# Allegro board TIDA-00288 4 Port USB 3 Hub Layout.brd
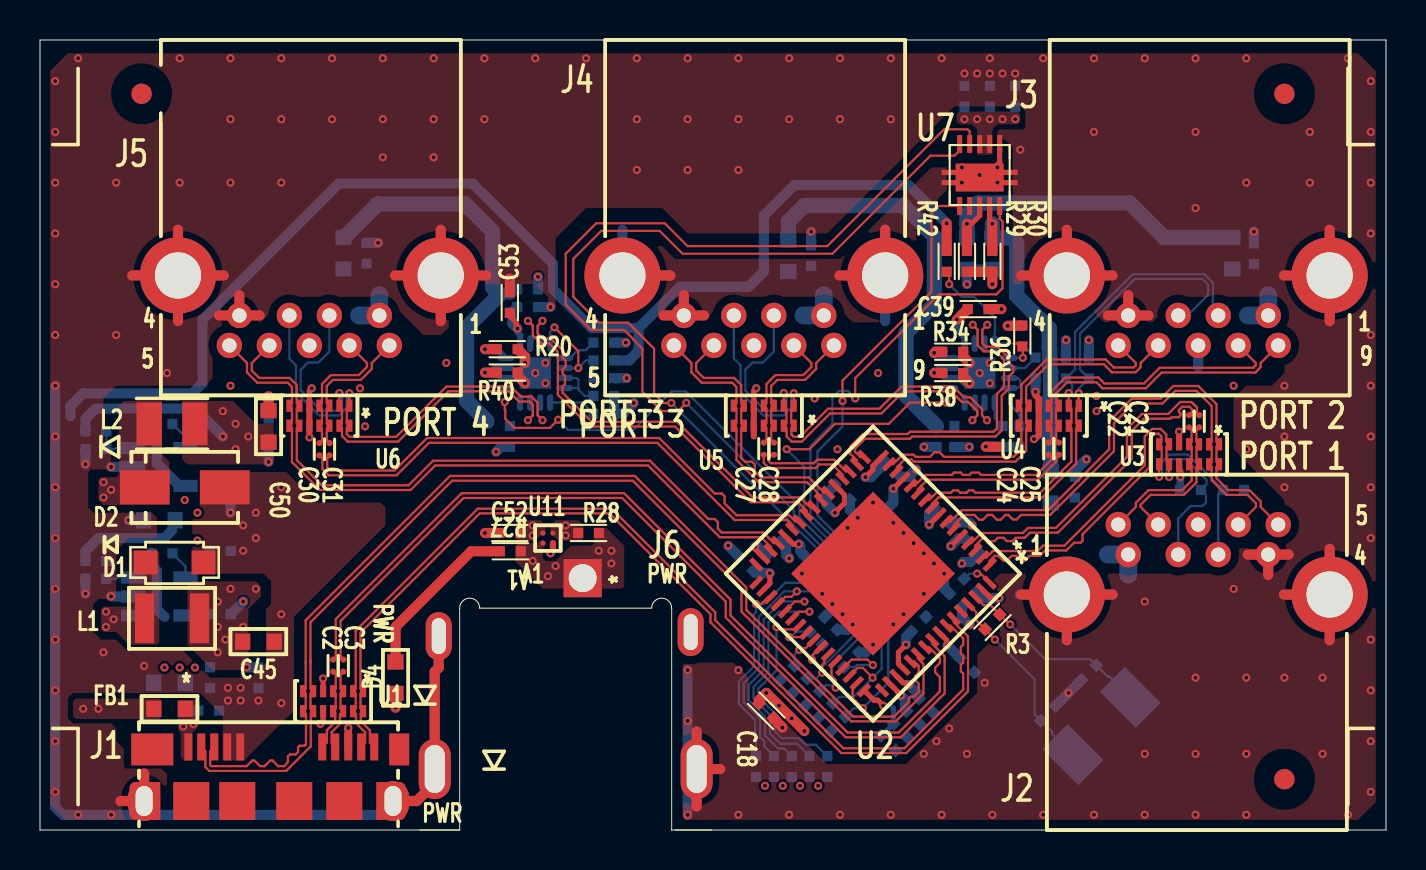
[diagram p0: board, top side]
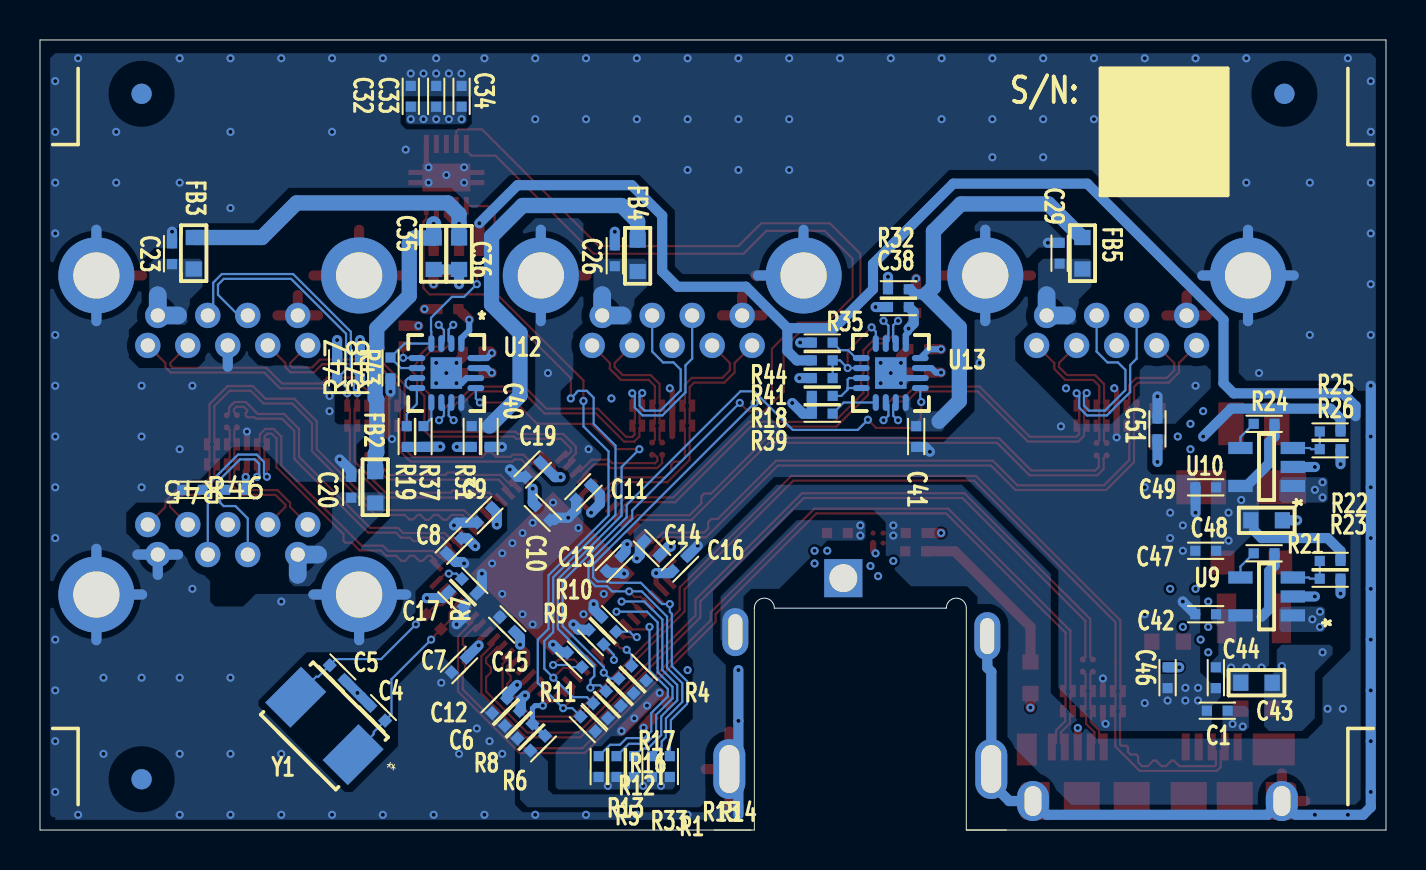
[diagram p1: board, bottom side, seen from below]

Outline 67.31 x 39.52 mm; copper layers: TOP, L2_GND, L3_PWR, BOTTOM. Coordinates in mm from the lower left corner of the outline.
Outline path: 0,0 0,39.52 67.31,39.52 67.31,0 31.75,0

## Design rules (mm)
net group DP_DN1: nets DM_DN1 DP_DN1
net group DP_DN2: nets DM_DN2 DP_DN2
net group DP_DN3: nets DM_DN3 DP_DN3
net group DP_DN4: nets DM_DN4 DP_DN4
net group DP_HUB_SSTX_P3: nets HUB_SSTXM_P3 HUB_SSTXP_P3
net group DP_HUB_SSTX_P4: nets HUB_SSTXM_P4 HUB_SSTXP_P4
net group DP_OUT3: nets DM_OUT3 DP_OUT3
net group DP_OUT4: nets DM_OUT4 DP_OUT4
net group DP_SSRX_DN1: nets SSRXM_DN1 SSRXP_DN1
net group DP_SSRX_DN2: nets SSRXM_DN2 SSRXP_DN2
net group DP_SSRX_DN3: nets SSRXM_DN3 SSRXP_DN3
net group DP_SSRX_DN4: nets SSRXM_DN4 SSRXP_DN4
net group DP_SSRX_UP: nets SSRXM_UP SSRXP_UP
net group DP_SSTX_DN1: nets SSTXM_DN1 SSTXP_DN1
net group DP_SSTX_DN2: nets SSTXM_DN2 SSTXP_DN2
net group DP_SSTX_DN3: nets SSTXM_DN3 SSTXP_DN3
net group DP_SSTX_DN4: nets SSTXM_DN4 SSTXP_DN4
net group DP_SSTX_P1: nets HUB_SSTXM_P1 HUB_SSTXP_P1
net group DP_SSTX_P2: nets HUB_SSTXM_P2 HUB_SSTXP_P2
net group DP_SSTX_PUP: nets SSTXM_PUP SSTXP_PUP
net group DP_SSTX_UP: nets SSTXM_UP SSTXP_UP
net group DP_UP: nets DM_UP DP_UP
nets with their own width: min track width 0.109; nets GRST#
nets with their own width: min track width 0.508; nets VBUS_IN VBUS_OUT_PORT_1 VBUS_OUT_PORT_2 VBUS_OUT_PORT_3 VBUS_OUT_PORT_4 VBUS_P1_FB VBUS_P2_FB VBUS_P3_FB VBUS_P4_FB VBUS_PUP_FB

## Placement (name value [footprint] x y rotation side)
C1  0.1uF  [0402]  8.44 5.97 0 bottom
C2  0.1uF  [0201RND]  14.66 8.23 90 top
C3  0.1uF  [0201RND]  15.17 8.23 90 top
C4  18pF  [0402]  50.42 5.84 45 bottom
C5  18pF  [0402]  52.45 7.87 225 bottom
C6  1uF  [0402]  43.69 5.59 315 bottom
C7  .01uF  [0402]  46.35 8.26 315 bottom
C8  .01uF  [0402]  46.61 14.22 315 bottom
C9  0.1uF  [0402]  45.09 15.75 315 bottom
C10  0.1uF  [0402]  42.16 15.88 225 bottom
C11  0.1uF  [0402]  40.13 16.89 315 bottom
C12  .01uF  [0402]  44.32 6.22 315 bottom
C13  .01uF  [0402]  38.61 13.34 315 bottom
C14  10uF  [0402]  36.7 14.1 45 bottom
C15  .01uF  [0402]  43.94 10.29 45 bottom
C16  .01uF  [0402]  35.31 13.34 135 bottom
C17  0.1uF  [0402]  46.48 11.56 225 bottom
C18  0.1uF  [0402]  36.32 5.97 315 top
C19  10uF  [0402]  42.67 18.03 315 bottom
C20  0.1uF  [0402]  51.75 17.15 90 bottom
C21  0.1uF  [0201RND]  57.97 20.45 90 top
C22  0.1uF  [0201RND]  57.46 20.45 90 top
C23  0.1uF  [0402]  60.71 28.83 90 bottom
C24  0.1uF  [0201RND]  50.45 19.08 270 top
C25  0.1uF  [0201RND]  50.95 19.08 270 top
C26  0.1uF  [0402]  38.57 28.73 90 bottom
C27  0.1uF  [0201RND]  36.2 19.08 270 top
C28  0.1uF  [0201RND]  36.7 19.08 270 top
C29  0.1uF  [0402]  16.32 28.85 90 bottom
C30  0.1uF  [0201RND]  13.97 19.05 270 top
C31  0.1uF  [0201RND]  14.48 19.05 270 top
C32  0.1uF  [0402]  48.77 36.7 90 bottom
C33  4.7uF  [0402]  47.5 36.7 90 bottom
C34  0.1uF  [0402]  46.23 36.7 90 bottom
C35  22uF  [0603]  47.62 28.83 270 bottom
C36  22uF  [0603]  46.35 28.83 270 bottom
C38  4.7uF  [0402]  24.38 26.16 0 bottom
C39  0.1uF  [0402]  46.91 26.06 0 top
C40  10uF  [0402]  44.83 19.69 270 bottom
C41  10uF  [0402]  23.5 19.69 270 bottom
C42  2.2uF  [0402]  9.02 10.8 0 bottom
C43  22uF  [0603]  6.48 7.37 180 bottom
C44  0.1uF  [0402]  8.51 7.62 270 bottom
C45  22uF  [0603]  10.92 9.42 0 top
C46  2.2uF  [0402]  10.92 7.62 270 bottom
C47  2.2uF  [0402]  9.02 13.97 0 bottom
C48  22uF  [0603]  5.97 15.49 180 bottom
C49  0.1uF  [0402]  9.02 17.15 0 bottom
C50  22uF  [0603]  11.43 20.19 90 top
C51  2.2uF  [0402]  11.43 20.07 90 bottom
C52  10uF  [0402]  23.5 14.86 180 top
C53  0.1uF  [0402]  23.5 26.39 90 top
D1  MBR0520LT1G  [SOD123F]  6.73 13.39 180 top
D2  B130-13-F  [SMA]  7.24 17.15 180 top
D4  LED  [0603]  17.78 7.62 90 top
FB1  220 @ 100MHZ, 2A  [0603]  6.48 6.07 180 top
FB2  220 @ 100MHZ,2A  [0603]  50.55 17.15 90 bottom
FB3  220 @ 100MHZ,2A  [0603]  59.62 28.85 90 bottom
FB4  220 @ 100MHZ,2A  [0603]  37.42 28.73 90 bottom
FB5  220 @ 100MHZ,2A  [0603]  15.18 28.85 90 bottom
J1  USB3_MICRO_B  [CON_SMRT_10_USB3_ZX360D-B]  11.43 1.45 0 top
J2  USB3_TYPEA_CONNECTOR  [USB3_TYPEA]  57.92 15.28 0 top
J3  USB3_TYPEA_CONNECTOR  [USB3_TYPEA]  57.92 24.24 180 top
J4  USB3_TYPEA_CONNECTOR  [USB3_TYPEA]  35.7 24.24 180 top
J5  USB3_TYPEA_CONNECTOR  [USB3_TYPEA]  13.47 24.24 180 top
J6  DC_PWR_JACK  [JACK_PJ-068]  27.14 12.59 90 top
L1  6.8uH@700mA  [1210]  6.6 10.59 0 top
L2  2.2uH@1.3A  [IND_1008]  6.6 20.32 0 top
NOREF  -  []  67.31 39.37 0 top
NOREF#2  -  []  20.95 29.08 0 top
NOREF#3  -  []  49.54 39.37 0 top
NOREF#4  -  []  0 0 0 top
NOREF#5  -  []  64.4 0 0 top
NOREF#6  -  []  67.31 39.37 0 top
NOREF#7  -  [unnamed#2]  62.23 36.83 0 top
NOREF#8  -  []  454.66 15.24 0 top
NOREF#9  -  []  0 0 0 top
NOREF#10  -  []  -25.4 -97.98 0 top
NOREF#11  -  []  0 0 0 top
NOREF#12  -  []  49.54 39.37 0 top
NOREF#13  -  []  67.31 39.37 0 top
NOREF#14  -  []  0 0 90 top
NOREF#15  -  []  67.31 39.37 0 top
NOREF#16  -  [unnamed#2]  5.08 36.83 0 top
NOREF#17  -  []  2.79 0.6 0 top
NOREF#18  -  []  21.37 11.59 0 top
NOREF#19  -  []  64.4 0 0 top
NOREF#20  -  []  0 39.52 0 top
NOREF#21  -  []  2.79 0.6 0 top
NOREF#22  -  []  27.93 39.37 0 top
NOREF#23  -  []  0 0 0 top
NOREF#24  -  []  0 0 0 top
NOREF#25  -  [unnamed#2]  62.23 2.54 0 top
NOREF#26  -  []  27.93 39.37 0 top
NOREF#27  -  []  0 0 90 top
NOREF#28  -  []  20.99 0 0 top
NOREF#29  -  [unnamed#2]  62.23 36.83 180 bottom
NOREF#30  -  []  21.26 34.93 180 bottom
NOREF#31  -  [unnamed#2]  62.23 2.54 180 bottom
NOREF#32  -  [unnamed#2]  5.08 36.83 180 bottom
NOREF#33  -  []  36.55 32.63 180 bottom
R1  DNI  [0402]  37.59 3.18 90 bottom
R3  DNI,1M  [0402]  47.62 10.41 45 top
R4  DNI  [0402]  37.36 7.85 45 bottom
R5  DNI  [0402]  39.37 3.18 90 bottom
R6  90.9K  [0402]  42.42 4.34 135 bottom
R7  9.1K  [0402]  45.85 12.19 225 bottom
R8  10k  [0402]  43.05 4.95 315 bottom
R9  10k  [0402]  39.5 9.65 45 bottom
R10  10k  [0402]  38.86 10.29 45 bottom
R11  10k  [0402]  40.58 8.52 45 bottom
R12  10k  [0402]  39.28 5.97 45 bottom
R13  10k  [0402]  39.9 5.31 45 bottom
R14  4.7K  [0402]  35.81 3.18 270 bottom
R15  4.7K  [0402]  36.7 3.18 270 bottom
R16  10k  [0402]  38.63 6.58 45 bottom
R17  10k  [0402]  38 7.21 45 bottom
R18  10k  [0402]  28.19 21.72 180 bottom
R19  10k  [0402]  48.97 19.69 90 bottom
R20  33.6K  [0402]  23.37 24.05 0 top
R21  10k  [0402]  6.1 13.84 0 bottom
R22  45.3K  [0402]  2.79 13.46 0 bottom
R23  10k  [0402]  2.79 12.57 180 bottom
R24  10k  [0402]  6.1 20.32 0 bottom
R25  8.25K  [0402]  2.79 19.94 0 bottom
R26  10k  [0402]  2.79 19.05 180 bottom
R27  290  [0402]  23.52 13.94 180 top
R28  10k  [0402]  27.43 14.86 180 top
R29  DNI  [0402]  47.62 28.45 90 top
R30  DNI  [0402]  46.35 28.45 90 top
R31  DNI  [0402]  45.72 19.69 90 bottom
R32  DNI  [0402]  24.38 27.05 180 bottom
R33  DNI  [0402]  38.48 3.18 90 bottom
R34  33.6K  [0402]  45.64 23.93 0 top
R35  10k  [0402]  28.19 24.38 180 bottom
R36  10k  [0402]  49.12 24.71 270 top
R37  10k  [0402]  48.13 19.69 90 bottom
R38  DNI  [0402]  45.64 22.86 0 top
R39  10k  [0402]  28.19 20.83 180 bottom
R40  DNI  [0402]  23.37 22.89 0 top
R41  47K  [0402]  28.19 22.61 0 bottom
R42  10k  [0402]  45.34 28.45 270 top
R43  47K  [0402]  49.78 23.11 270 bottom
R44  10k  [0402]  28.19 23.5 180 bottom
R45  62K  [0402]  59.69 17.02 0 bottom
R46  62K  [0402]  57.53 17.02 180 bottom
R47  62K  [0402]  52.45 23.11 90 bottom
R48  62K  [0402]  51.31 23.11 90 bottom
U1  TPD6E05U06  [UQFN_14_142X57_20]  14.66 6.45 180 top
U2  TUSB8041  [QFN_64_354SQ_20]  41.66 12.83 225 top
U3  TPD6E05U06  [UQFN_14_142X57_20]  57.46 18.8 180 top
U4  TPD6E05U06  [UQFN_14_142X57_20]  50.45 20.73 180 top
U5  TPD6E05U06  [UQFN_14_142X57_20]  36.2 20.73 180 top
U6  TPD6E05U06  [UQFN_14_142X57_20]  13.97 20.73 180 top
U7  TPS2003C  [DRC_S_PDSO_N10]  46.99 32.77 270 top
U9  LMR10510X  [SOT_23_5]  5.97 11.68 90 bottom
U10  LMR10510X  [SOT_23_5]  5.97 18.16 90 bottom
U11  TPS22910  [BGA_4_36SQ_20]  25.4 14.61 270 top
U12  TPS2546  [QFN_16_124X124_20]  46.99 22.86 270 bottom
U13  TPS2546  [QFN_16_124X124_20]  24.77 22.86 270 bottom
Y1  24MHz  [XTAL_2_SM_197X126]  53.09 5.21 45 bottom

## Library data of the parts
C1-C36 C38-C53 = CAP NP
D1 D2 = DIODE SCHOTTKY
D4 = LED
FB1-FB5 = FERRITE BEAD
J1 = USB3_MICRO_B
J2-J5 = USB3_TYPEA_CONNECTER
J6 = 6140046600_DC_PWR_JACK_0
L1 L2 = INDUCTOR
R1 R3-R48 = R
U1 U3-U6 = TPD6E05U06
U2 = TUSB8041
U7 = TPS2003C
U9 U10 = LMR10510X
U11 = TPS22910
U12 U13 = TPS2546
Y1 = CRYSTAL

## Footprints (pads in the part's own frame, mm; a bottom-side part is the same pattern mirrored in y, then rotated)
0201RND
  round 0.305 smd: 1(-0.305,0) 2(0.305,0)
0402
  rect 0.508x0.508 smd: 1(-0.521,0) 2(0.521,0)
0603
  rect 0.762x0.813 smd: 1(-0.787,0) 2(0.787,0)
1210
  rect 0.965x2.489 smd: 1(-1.372,0) 2(1.372,0)
BGA_4_36SQ_20
  round 0.254 smd: A1(0.25,-0.25) A2(-0.25,-0.25) B1(0.25,0.25) B2(-0.25,0.25)
CON_SMRT_10_USB3_ZX360D-B
  rect 2.1x1.6 smd: (-5.815,2.58)
  rect 1.8x1.9 smd: (-3.865,0) (-1.565,0) (1.285,0) (3.785,0)
  rect 1x1.6 smd: (6.535,2.58)
  rect 0.4x1.35 smd: 1(-4.015,2.705) 2(-3.365,2.705) 3(-2.715,2.705) 4(-2.065,2.705) 5(-1.415,2.705) 6(2.685,2.705) 7(3.335,2.705) 8(3.985,2.705) 9(4.635,2.705) 10(5.285,2.705)
  oval 1.6x2 hole 0.85x1.5: 11(-6.223,0) 12(6.223,0)
DRC_S_PDSO_N10
  rect 0.9x0.25 smd: 1(-1.55,1) 2(-1.55,0.5) 3(-1.55,0) 4(-1.55,-0.5) 5(-1.55,-1) 6(1.55,-1) 7(1.55,-0.5) 8(1.55,0) 9(1.55,0.5) 10(1.55,1)
  custom 0.35x0.35 smd: 11(0.125,0)
IND_1008
  rect 1.27x2.146 smd: 1(-1.143,0) 2(1.143,0)
JACK_PJ-068
  rect 1.905x1.905 hole 1.397: 1(0.005,0)
  oval 2.4x1.3 hole 1.8x0.7: 2(-2.895,7.2) 3(-2.695,-5.4)
  oval 3x1.6 hole 2.4x1: 4(-9.545,-5.7) 5(-9.545,7.4)
QFN_16_124X124_20
  oval 0.838x0.305 smd: 1(-1.475,0.75) 2(-1.475,0.25) 3(-1.475,-0.25) 4(-1.475,-0.75) 9(1.475,-0.75) 10(1.475,-0.25) 11(1.475,0.25) 12(1.475,0.75)
  oval 0.305x0.838 smd: 5(-0.75,-1.475) 6(-0.25,-1.475) 7(0.25,-1.475) 8(0.75,-1.475) 13(0.75,1.475) 14(0.25,1.475) 15(-0.25,1.475) 16(-0.75,1.475)
  rect 1.575x1.575 smd: 17(0,0)
QFN_64_354SQ_20
  rect 0.787x0.254 smd: 1(-4.445,3.81) 2(-4.445,3.302) 3(-4.445,2.794) 4(-4.445,2.286) 5(-4.445,1.778) 6(-4.445,1.27) 7(-4.445,0.762) 8(-4.445,0.254) 9(-4.445,-0.254) 10(-4.445,-0.762) 11(-4.445,-1.27) 12(-4.445,-1.778) 13(-4.445,-2.286) 14(-4.445,-2.794) 15(-4.445,-3.302) 16(-4.445,-3.81) 33(4.445,-3.81) 34(4.445,-3.302) 35(4.445,-2.794) 36(4.445,-2.286) 37(4.445,-1.778) 38(4.445,-1.27) 39(4.445,-0.762) 40(4.445,-0.254) 41(4.445,0.254) 42(4.445,0.762) 43(4.445,1.27) 44(4.445,1.778) 45(4.445,2.286) 46(4.445,2.794) 47(4.445,3.302) 48(4.445,3.81)
  rect 0.254x0.787 smd: 17(-3.81,-4.445) 18(-3.302,-4.445) 19(-2.794,-4.445) 20(-2.286,-4.445) 21(-1.778,-4.445) 22(-1.27,-4.445) 23(-0.762,-4.445) 24(-0.254,-4.445) 25(0.254,-4.445) 26(0.762,-4.445) 27(1.27,-4.445) 28(1.778,-4.445) 29(2.286,-4.445) 30(2.794,-4.445) 31(3.302,-4.445) 32(3.81,-4.445) 49(3.81,4.445) 50(3.302,4.445) 51(2.794,4.445) 52(2.286,4.445) 53(1.778,4.445) 54(1.27,4.445) 55(0.762,4.445) 56(0.254,4.445) 57(-0.254,4.445) 58(-0.762,4.445) 59(-1.27,4.445) 60(-1.778,4.445) 61(-2.286,4.445) 62(-2.794,4.445) 63(-3.302,4.445) 64(-3.81,4.445)
  rect 5.791x5.791 smd: 65(0,0)
SMA
  rect 2.489x1.702 smd: 1(-2,0) 2(2,0)
SOD123F
  rect 1.194x1.194 smd: 1(-1.448,0) 2(1.448,0)
SOT_23_5
  rect 0.61x1.219 smd: 1(-0.95,-1.31) 2(0,-1.31) 3(0.95,-1.31) 4(0.95,1.31) 5(-0.95,1.31)
unnamed#2
  round 1.016 smd: (0,0)
UQFN_14_142X57_20
  rect 0.305x0.61 smd: 1(-1.5,-0.5) 2(-1,-0.5) 3(-0.5,-0.5) 4(0,-0.5) 5(0.5,-0.5) 6(1,-0.5) 7(1.5,-0.5) 8(1.5,0.5) 9(1,0.5) 10(0.5,0.5) 11(0,0.5) 12(-0.5,0.5) 13(-1,0.5) 14(-1.5,0.5)
USB3_TYPEA
  round 1.27 hole 0.711: 1(-3.5,-1.5) 2(-1,-1.5) 3(1,-1.5) 4(3.5,-1.5) 5(4,0) 6(2,0) 7(0,0) 8(-2,0) 9(-4,0)
  round 3.81 hole 2.311: 10(-6.57,-3.5) 11(6.57,-3.5)
XTAL_2_SM_197X126
  rect 1.778x2.54 smd: 1(-2.032,0) 2(2.032,0)

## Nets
GND: C1.2 C4.2 C5.2 C6.2 C7.2 C8.2 C9.2 C10.2 C11.2 C12.2 C13.2 C14.2 C15.2 C16.2 C17.2 C18.2 C19.2 C20.2 C23.2 C26.2 C29.2 C32.2 C33.2 C34.2 C35.2 C36.2 C38.2 C39.2 C40.2 C41.2 C42.2 C43.2 C44.2 C45.2 C46.2 C47.2 C48.2 C49.2 C50.2 C51.2 C52.2 C53.2 D1.1(ANODE) D2.1(ANODE) D4.1(CATHODE) J1.4(USB_OTG) J1.5(GND) J1.8(GND1) J1.11(SLD1) J1.12(SLD2) J2.4(GND#4) J2.7(GND#7) J2.10(SHIELD0) J2.11(SHIELD1) J3.4(GND#4) J3.7(GND#7) J3.10(SHIELD0) J3.11(SHIELD1) J4.4(GND#4) J4.7(GND#7) J4.10(SHIELD0) J4.11(SHIELD1) J5.4(GND#4) J5.7(GND#7) J5.10(SHIELD0) J5.11(SHIELD1) J6.2(GND) J6.4(G1) J6.5(G2) R7.2 R8.2 R9.2 R10.2 R11.2 R20.2 R23.2 R26.2 R34.2 R38.2 R40.2 R41.2 R43.2 R45.2 R46.2 R47.2 R48.2 U1.5(GND5) U1.10(GND10) U2.65(PAD) U3.5(GND5) U3.10(GND10) U4.5(GND5) U4.10(GND10) U5.5(GND5) U5.10(GND10) U6.5(GND5) U6.10(GND10) U7.1(GND) U7.11(PAD) U9.2(GND) U10.2(GND) U11.B1(GND) U12.14(GND) U12.17(PAD) U13.14(GND) U13.17(PAD)
VBUS_IN: C52.1 FB1.2 R6.1 R42.1 R44.1 U11.A2(VIN)
VBUS_OUT_PORT_1: C35.1 FB2.2 R29.2 U7.9(OUT1)
VBUS_OUT_PORT_2: C36.1 FB3.2 R30.2 U7.8(OUT2)
VBUS_OUT_PORT_3: C40.1 FB4.2 R31.2 U12.12(VOUT)
VBUS_OUT_PORT_4: C41.1 FB5.2 R32.2 U13.12(VOUT)
VBUS_P1_FB: C20.1 FB2.1 J2.1(VBUS)
VBUS_P2_FB: C23.1 FB3.1 J3.1(VBUS)
VBUS_P3_FB: C26.1 FB4.1 J4.1(VBUS)
VBUS_P4_FB: C29.1 FB5.1 J5.1(VBUS)
VBUS_PUP_FB: C1.1 FB1.1 J1.1(VBUS)
2546_EN_PORT3: R36.2 U12.5(EN)
2546_EN_PORT4: R35.2 U13.5(EN)
AUTO_EN: R11.1 U2.45(AUTOEN/HS_SUSPD)
BOARD_1P1V: C7.1 C8.1 C9.1 C10.1 C11.1 C12.1 C13.1 C14.1 C50.1 C51.1 L2.2 R25.1 U2.5(VDD1) U2.8(VDD2) U2.13(VDD3) U2.21(VDD4) U2.28(VDD5) U2.31(VDD6) U2.51(VDD7) U2.57(VDD8)
BOARD_3P3V: C15.1 C16.1 C17.1 C18.1 C19.1 C45.1 C46.1 C47.1 C48.1 C49.1 L1.2 R1.1 R4.1 R5.1 R12.1 R13.1 R14.2 R15.2 R16.1 R17.1 R22.1 R24.1 R33.1 U2.16(VDD33_1) U2.34(VDD33_2) U2.52(VDD33_3) U2.63(VDD33_4) U10.5(VIN)
BOARD_5V: C32.1 C33.1 C34.1 C38.1 C39.1 C42.1 C43.1 C44.1 C53.1 J6.1(+IN) R18.1 R19.1 R21.1 R27.1 R28.1 R29.1 R30.1 R31.1 R32.1 R35.1 R36.1 R37.1 R39.1 U7.2(IN1) U7.3(IN2) U9.5(VIN) U11.A1(VOUT) U12.1(VIN) U13.1(VIN)
DM_DN1: J2.2(DM) R46.1 U2.2(USB_DM_DN1) U3.6(NC6) U3.9(D3+)
DM_DN2: J3.2(DM) R48.1 U2.10(USB_DM_DN2) U4.2(NC2) U4.13(D1-)
DM_DN3: U2.18(USB_DM_DN3) U12.2(DM_OUT)
DM_DN4: U2.25(USB_DM_DN4) U13.2(DM_OUT)
DM_OUT3: J4.2(DM) U5.2(NC2) U5.13(D1-) U12.11(DM_IN)
DM_OUT4: J5.2(DM) U6.2(NC2) U6.13(D1-) U13.11(DM_IN)
DM_UP: J1.2(D-) U1.6(NC6) U1.9(D3+) U2.54(USB_DM_UP)
DP_DN1: J2.3(DP) R45.1 U2.1(USB_DP_DN1) U3.7(NC7) U3.8(D3-)
DP_DN2: J3.3(DP) R47.1 U2.9(USB_DP_DN2) U4.1(NC1) U4.14(D1+)
DP_DN3: U2.17(USB_DP_DN3) U12.3(DP_OUT)
DP_DN4: U2.24(USB_DP_DN4) U13.3(DP_OUT)
DP_OUT3: J4.3(DP) U5.1(NC1) U5.14(D1+) U12.10(DP_IN)
DP_OUT4: J5.3(DP) U6.1(NC1) U6.14(D1+) U13.10(DP_IN)
DP_UP: J1.3(D+) U1.7(NC7) U1.8(D3-) U2.53(USB_DP_UP)
EN_PORT1: R15.1 U2.36(PWRCTL1/BATEN1) U7.4(EN1)
EN_PORT2: R14.1 U2.35(PWRCTL2/BATEN2) U7.5(EN2)
EN_PORT3: U2.33(PWRCTL3/BATEN3)
EN_PORT4: U2.32(PWRCTL4/BATEN4)
FLT_PORT1#: R12.2 U2.46(OVERCURZ1) U7.10(FLT1#)
FLT_PORT2#: R13.2 U2.47(OVERCURZ2) U7.6(FLT2#)
FLT_PORT3#: R16.2 U2.44(OVERCURZ3) U12.13(FAULT#)
FLT_PORT4#: R17.2 U2.43(OVERCURZ4) U13.13(FAULT#)
GANGED: R9.1 U2.42(GANGED/SMBA2/HS_UP)
GRST#: C6.1 U2.50(GRST#)
HUB_SSTXM_P1: C21.1 J2.8(SSTXN) U3.3(NC3) U3.12(D2+)
HUB_SSTXM_P2: C24.1 J3.8(SSTXN) U4.4(NC4) U4.11(D2-)
HUB_SSTXM_P3: C27.1 J4.8(SSTXN) U5.4(NC4) U5.11(D2-)
HUB_SSTXM_P4: C30.1 J5.8(SSTXN) U6.4(NC4) U6.11(D2-)
HUB_SSTXP_P1: C22.1 J2.9(SSTXP) U3.4(NC4) U3.11(D2-)
HUB_SSTXP_P2: C25.1 J3.9(SSTXP) U4.3(NC3) U4.12(D2+)
HUB_SSTXP_P3: C28.1 J4.9(SSTXP) U5.3(NC3) U5.12(D2+)
HUB_SSTXP_P4: C31.1 J5.9(SSTXP) U6.3(NC3) U6.12(D2+)
I2C_ENABLE: R5.2 U2.39(SMBUSZ/SS_SUPD)
I2C_SCL: R33.2 U2.38(SCL/SMBCLK)
I2C_SDA: R1.2 U2.37(SDA/SMBDAT)
JACK_INSERT: J6.3(GND#3) R28.2 U11.B2(ON)
PORT3_CTL1_ILIM_SEL: R42.2 R43.1 U12.4(ILIM_SEL) U12.6(CLT1)
PORT3_CTL2_CTL3: R19.2 U12.7(CLT2) U12.8(CLT3)
PORT3_STATUS#: R37.2 U12.9(STATUS#)
PORT4_CTL1_ILIM_SEL: R41.1 R44.2 U13.4(ILIM_SEL) U13.6(CLT1)
PORT4_CTL2_CTL3: R18.2 U13.7(CLT2) U13.8(CLT3)
PORT4_STATUS#: R39.2 U13.9(STATUS#)
PWRCTL_POL: R4.2 U2.41(PWRCTL_POL)
PWRMGMT_EN#: R10.1 U2.40(FPMGT/SMBA1/SS_UP)
SSRXM_DN1: J2.5(SSRXN) U2.7(USB_SSRXM_DN1) U3.1(NC1) U3.14(D1+)
SSRXM_DN2: J3.5(SSRXN) U2.15(USB_SSRXM_DN2) U4.7(NC7) U4.8(D3-)
SSRXM_DN3: J4.5(SSRXN) U2.23(USB_SSRXM_DN3) U5.7(NC7) U5.8(D3-)
SSRXM_DN4: J5.5(SSRXN) U2.30(USB_SSRXM_DN4) U6.7(NC7) U6.8(D3-)
SSRXM_UP: J1.10(RX+) U1.1(NC1) U1.14(D1+) U2.59(USB_SSRXM_UP)
SSRXP_DN1: J2.6(SSRXP) U2.6(USB_SSRXP_DN1) U3.2(NC2) U3.13(D1-)
SSRXP_DN2: J3.6(SSRXP) U2.14(USB_SSRXP_DN2) U4.6(NC6) U4.9(D3+)
SSRXP_DN3: J4.6(SSRXP) U2.22(USB_SSRXP_DN3) U5.6(NC6) U5.9(D3+)
SSRXP_DN4: J5.6(SSRXP) U2.29(USB_SSRXP_DN4) U6.6(NC6) U6.9(D3+)
SSRXP_UP: J1.9(RX-) U1.2(NC2) U1.13(D1-) U2.58(USB_SSRXP_UP)
SSTXM_DN1: C21.2 U2.4(USB_SSTXM_DN1)
SSTXM_DN2: C24.2 U2.12(USB_SSTXM_DN2)
SSTXM_DN3: C27.2 U2.20(USB_SSTXM_DN3)
SSTXM_DN4: C30.2 U2.27(USB_SSTXM_DN4)
SSTXM_PUP: C2.1 J1.6(TX-) U1.4(NC4) U1.11(D2-)
SSTXM_UP: C3.2 U2.56(USB_SSTXM_UP)
SSTXP_DN1: C22.2 U2.3(USB_SSTXP_DN1)
SSTXP_DN2: C25.2 U2.11(USB_SSTXP_DN2)
SSTXP_DN3: C28.2 U2.19(USB_SSTXP_DN3)
SSTXP_DN4: C31.2 U2.26(USB_SSTXP_DN4)
SSTXP_PUP: C3.1 J1.7(TX+) U1.3(NC3) U1.12(D2+)
SSTXP_UP: C2.2 U2.55(USB_SSTXP_UP)
USB_R1: R7.1 U2.64(USB_R1)
USB_VBUS_UP: R6.2 R8.1 U2.48(USB_VBUS)
XI: C5.1 R3.2 U2.62(XI) Y1.2
XO: C4.1 R3.1 U2.61(XO) Y1.1
N15283: R21.2 U9.4(EN)
N15348: D1.2(CATHODE) L1.1 U9.1(SW)
N15491: R22.2 R23.1 U9.3(FB)
N16295: R24.2 U10.4(EN)
N16337: D2.2(CATHODE) L2.1 U10.1(SW)
N16409: R25.2 R26.1 U10.3(FB)
N16775579: D4.2(ANODE) R27.2
N16809594: R34.1 U12.16(ILIM_HI)
N16810447: R20.1 U13.16(ILIM_HI)
N16811536: R38.1 U12.15(ILIM_LO)
N16811977: R40.1 U13.15(ILIM_LO)

Pads without a net: U2 49 60; U7 7

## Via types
v1: diameter 0.406, hole 0.203, TOP to BOTTOM, 350 vias

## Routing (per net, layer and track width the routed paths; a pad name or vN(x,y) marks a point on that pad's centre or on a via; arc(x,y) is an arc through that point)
GND: length 336.3
  TOP w0.254: v1(14.02,5.31) 14.02,5.33 14.16,5.46 U1.10 ; 47.99,34.32 U7.1 47.99,33.4 47.88,33.29 v1(47.88,33.15) ; v1(35.81,22.1) 35.7,21.98 U5.5 ; U6.5 13.47,21.98 v1(13.59,22.1) ; U1.5 v1(14.16,7.58)
  TOP w0.305: U3.10 56.96,17.99 57.02,17.93 v1(57.02,17.66) ; U3.5 v1(56.96,19.93) ; 35.7,19.69 U5.10 U5.5 ; v1(25.53,13.84) 25.65,13.97 U11.B1 ; v1(49.78,21.93) 49.78,21.74 49.95,21.58 U4.5 U4.10 49.95,19.74 49.76,19.56 v1(49.71,19.56) ; v1(13.47,19.64) U6.10 U6.5
  TOP w0.381: J1.8 v1(15.42,5.11)
  TOP w0.508: 53.4,25.74 J3.4 ; J3.4 55.44,25.74 ; J3.4 54.42,26.76 ; J6.4 34.02,3.05 ; J6.4 32.84,4.93 ; J6.4 32.84,1.17 ; C39.2 v1(48.08,26.06) ; 20.04,25.46 J5.10 ; J5.10 20.04,30.03 ; J5.10 17.75,27.74 ; J5.10 22.33,27.74 ; J5.11 6.9,30.03 ; J5.11 4.61,27.74 ; J5.11 6.9,25.46 ; J5.11 9.19,27.74 ; J2.4 62.44,13.78 ; J2.4 60.4,13.78 ; J2.4 61.42,12.76 ; J2.10 53.64,11.78 ; J2.10 51.35,9.49 ; J2.10 49.06,11.78 ; 64.49,25.46 J3.10 ; J3.10 64.49,30.03 ; J3.10 62.2,27.74 ; J6.2 19.94,8.12 19.74,7.92 J6.5 19.74,2.35 18.84,1.45 J1.12 ; v1(24.26,23.37) 24.26,23.69 R20.2 ; R34.2 46.16,23.69 v1(46.48,23.37) ; 31.52,27.74 31.52,27.74 J4.11 ; 5.21,2.83 J1.11 4.03,1.45 ; J4.4 33.21,25.74 ; J4.4 32.2,26.76 ; J4.4 31.18,25.74 ; R38.2 46.16,22.67 v1(46.48,22.35) ; 64.49,9.49 J2.11 ; J2.11 64.49,14.07 ; J2.11 62.2,11.78 ; C50.2 v1(11.43,21.69) ; C53.2 v1(23.5,27.58) ; C52.2 v1(22.25,14.86) ; J5.4 10.99,25.74 ; J5.4 9.97,26.76 ; J5.4 8.95,25.74 ; v1(24.26,22.35) 23.94,22.67 R40.2 ; J3.11 53.64,27.74 ; J3.11 49.06,27.74 ; J3.11 51.35,30.03 ; C18.2 36.69,5.58 37.11,5.16 37.11,5.14 v1(37.13,5.12) ; 39.98,27.74 J4.10 42.27,30.03 ; D4.1 v1(17.78,6.12)
  L2_GND w0.889: 6.9,25.66 J5.11 ; J5.11 8.98,27.74 ; J5.11 4.82,27.74 ; J5.11 6.9,29.83 ; J4.4 33.01,25.74 ; J4.4 31.38,25.74 ; J4.4 32.2,26.56 ; J3.10 64.49,29.83 ; J3.10 62.41,27.74 ; J3.10 64.49,25.66 ; 32.84,1.37 J6.4 ; J6.4 33.82,3.05 ; J6.4 32.84,4.73 ; J6.5 19.74,4.73 ; J6.5 19.74,1.37 ; J6.5 18.76,3.05 ; 61.42,12.97 J2.4 ; J2.4 60.61,13.78 ; J2.4 62.23,13.78 ; J1.12 17.65,2.63 ; J1.12 18.63,1.45 ; J1.12 16.68,1.45 ; 57.92,14.47 J2.7 57.92,16.09 ; 35.7,25.06 J4.7 35.7,23.43 ; J4.11 29.13,29.83 ; J4.11 31.21,27.74 ; J4.11 29.13,25.66 ; J4.11 27.04,27.74 ; 40.18,27.74 J4.10 ; J4.10 42.27,29.83 ; J4.10 44.35,27.74 ; J4.10 42.27,25.66 ; 57.92,23.43 J3.7 57.92,25.06 ; 62.41,11.78 J2.11 ; J2.11 64.49,13.86 ; J2.11 64.49,9.7 ; J5.10 20.04,29.83 ; J5.10 17.96,27.74 ; J5.10 20.04,25.66 ; J5.10 22.12,27.74 ; 19.94,8.32 J6.2 ; J6.2 19.11,9.7 ; J6.2 19.94,11.08 ; 51.35,25.66 J3.11 ; J3.11 51.35,29.83 ; J3.11 49.27,27.74 ; J3.11 53.43,27.74 ; J5.4 9.97,26.56 ; J5.4 9.16,25.74 ; J5.4 10.78,25.74 ; J3.4 54.42,26.56 ; J3.4 53.61,25.74 ; J3.4 55.23,25.74 ; 4.23,1.45 J1.11 ; J1.11 6.18,1.45 ; J1.11 5.21,2.63 ; 13.47,23.43 J5.7 13.47,25.06 ; J2.10 53.43,11.78 ; J2.10 51.35,13.86 ; J2.10 51.35,9.7 ; J2.10 49.27,11.78
  BOTTOM w0.305: U12.14 45.97,22.61 46.23,22.35 v1(46.48,22.35) ; v1(24.26,22.35) 24,22.61 U13.14
  BOTTOM w0.381: v1(57.02,17.66) 57.02,17.03 R46.2
  BOTTOM w0.508: R11.2 41.27,8.88 v1(41.66,9.27) ; C23.2 v1(60.71,29.93) ; 64.49,30.03 J3.10 64.49,25.46 ; C17.2 46.11,10.66 v1(46.48,10.29) ; 20.04,30.03 J5.10 20.04,25.46 ; v1(38.1,12.83) 38.19,12.83 38.23,12.87 38.88,12.87 C13.2 ; J2.11 64.49,14.07 ; J2.11 62.2,11.78 ; J2.11 64.49,9.49 ; 29.13,30.03 J4.11 31.41,27.74 ; 42.27,30.03 J4.10 42.27,25.46 ; 61.42,12.76 J2.4 ; J2.4 60.4,13.78 ; J2.4 62.44,13.78 ; v1(2.27,11.82) R23.2 ; v1(10.16,11.43) 10.16,11.42 C42.2 ; J5.11 6.9,30.03 ; J5.11 4.61,27.74 ; J5.11 6.9,25.46 ; J5.11 9.19,27.74 ; C51.2 v1(11.43,21.69) ; J2.10 48.99,11.78 ; J2.10 53.64,11.78 ; J2.10 51.35,9.49 ; J3.7 57.92,23.17 ; C16.2 v1(34.42,14.22) ; v1(9.53,15.88) 9.53,17.13 C49.2 ; v1(37.47,13.59) 37.47,13.61 37.31,13.76 37.31,14.22 C14.2 ; v1(43.81,18.03) 43.8,18.03 43.43,17.67 C19.2 ; R26.2 v1(2.27,18.3) ; R9.2 40.37,10.02 v1(40.64,10.29) ; C8.2 46.53,13.41 46.17,13.41 v1(46.1,13.34) ; C10.2 41.59,15.51 41.48,15.62 v1(40.89,15.62) 40.5,16.01 C11.2 ; C38.2 v1(25.53,26.16) ; v1(49.78,21.93) R43.2 ; U10.2 v1(3.56,18.16) ; v1(32.38,8) v1(32.38,5.46) 32.38,3.51 32.84,3.05 J6.4 32.38,2.6 v1(32.38,0.76) ; v1(45.21,12.83) 45.21,12.09 R7.2 ; v1(22.81,18.92) 23.05,19.16 C41.2 ; J6.2 19.94,8.12 19.74,7.92 J6.5 19.74,2.35 18.84,1.45 J1.12 16.97,0.76 5.92,0.76 5.23,1.45 J1.11 4.52,0.76 v1(3.56,0.76) v1(1.91,0.76) 1.14,0.76 0.76,1.14 v1(0.76,1.91) v1(0.76,4.45) v1(0.76,6.99) v1(0.76,9.53) v1(0.76,12.07) v1(0.76,14.61) v1(0.76,17.15) v1(0.76,19.69) v1(0.76,22.23) ; C29.2 v1(16.91,29.38) ; C4.2 51.24,6.66 v1(51.44,6.86) C5.2 ; C9.2 46.47,15.38 v1(46.61,15.24) ; C20.2 51.75,17.97 v1(52.32,18.54) ; C48.2 v1(4.45,15.49) ; R10.2 39.62,11.05 v1(39.62,11.3) ; R47.2 v1(52.45,24.51) ; C15.2 44.31,10.69 ; R48.2 v1(51.31,24.51) ; v1(46.35,27.31) C36.2 C35.2 ; C26.2 v1(38.57,29.93) ; R41.2 v1(29.34,22.61) ; C40.2 v1(44.21,19.16) ; U9.2 v1(3.56,11.68)
  vias: v1(0.76,37.47) v1(0.76,34.93) v1(0.76,32.39) v1(0.76,29.85) v1(0.76,27.31) v1(0.76,24.77) v1(1.91,38.61) v1(3.17,8.89) v1(3.81,32.39) v1(3.81,24.77) v1(5.21,8.2) v1(6.35,22.86) v1(6.99,38.61) v1(6.99,32.39) v1(9.4,7.11) v1(9.4,6.48) v1(9.53,38.61) v1(9.53,35.56) v1(9.53,32.39) v1(9.53,22.23) v1(10.03,7.11) v1(10.03,6.48) v1(10.16,15.24) v1(10.16,13.97) v1(10.79,15.88) v1(10.79,14.61) v1(10.92,6.48) v1(12.06,38.61) v1(12.06,35.56) v1(12.06,32.39) v1(12.06,17.15) v1(12.06,10.8) v1(12.06,6.35) v1(14.61,38.61) v1(14.61,35.56) v1(16,22.1) v1(16.26,20.19) v1(17.14,38.61) v1(17.14,35.56) v1(17.14,33.66) v1(19.68,38.61) v1(19.68,35.56) v1(19.68,33.66) v1(20.32,23.37) v1(22.23,38.61) v1(22.23,35.56) v1(24.77,38.61) v1(24.77,22.86) v1(25.27,23.37) v1(25.27,22.35) v1(27.3,38.61) v1(29.84,38.61) v1(29.84,35.56) v1(29.84,33.02) v1(32.38,38.61) v1(32.38,35.56) v1(32.38,33.02) v1(34.92,38.61) v1(34.92,35.56) v1(34.92,33.02) v1(34.92,8) v1(34.92,0.76) v1(37.47,38.61) v1(37.47,35.56) v1(37.47,0.76) v1(38.73,21.59) v1(39.12,11.81) v1(39.88,19.05) v1(40.01,38.61) v1(40.01,35.56) v1(40.01,0.76) v1(40.13,10.8) v1(40.39,15.11) v1(41.66,16.38) v1(41.91,22.86) v1(42.55,38.61) v1(42.55,35.56) v1(42.55,0.76) v1(42.67,15.37) v1(42.67,10.29) v1(43.18,14.86) v1(43.18,10.8) v1(43.69,14.35) v1(44.2,13.84) v1(44.2,11.81) v1(44.2,3.81) v1(44.7,13.34) v1(44.83,4.45) v1(45.09,38.61) v1(45.09,0.76) v1(45.47,5.08) v1(46.1,33.15) v1(46.1,32.39) v1(46.23,37.85) v1(46.35,3.81) v1(46.86,37.85) v1(46.99,32.77) v1(46.99,22.86) v1(47.24,7.37) v1(47.5,38.61) v1(47.5,37.85) v1(47.5,23.37) v1(47.5,22.35) v1(47.62,0.76) v1(47.88,32.39) v1(48.13,37.85) v1(48.77,37.85) v1(49.02,34.04) v1(50.16,38.61) v1(50.16,0.76) v1(52.7,38.61) v1(52.7,34.93) v1(52.7,0.76) v1(52.83,21.72) v1(52.83,20.96) v1(55.24,38.61) v1(55.24,11.43) v1(55.24,3.81) v1(55.24,0.76) v1(57.78,38.61) v1(57.78,34.93) v1(57.78,31.12) v1(57.78,7.62) v1(57.78,3.81) v1(57.78,0.76) v1(59.69,22.23) v1(59.69,12.07) v1(60.33,38.61) v1(60.33,32.39) v1(60.33,19.05) v1(60.33,7.62) v1(60.33,3.81) v1(60.33,0.76) v1(62.23,22.23) v1(62.23,19.69) v1(62.23,17.15) v1(62.23,7.62) v1(63.5,34.93) v1(63.5,32.39) v1(64.14,7.62) v1(64.14,3.81) v1(65.41,38.61) v1(65.41,0.76) v1(66.55,37.47) v1(66.55,34.93) v1(66.55,32.39) v1(66.55,29.85) v1(66.55,24.77) v1(66.55,22.23) v1(66.55,19.69) v1(66.55,17.15) v1(66.55,14.61) v1(66.55,9.53) v1(66.55,6.99) v1(66.55,4.45) v1(66.55,1.91)
VBUS_IN: length 63.9
  TOP w0.508: R42.1 v1(45.34,30.35)
  BOTTOM w0.508: v1(45.34,30.35) 43.43,32.26 37.72,32.26 36.2,30.73 36.2,27.94 35.43,27.18 32,27.18 29.93,25.11 ; R44.1 29.46,23.5 29.93,23.97 29.93,25.11 ; 1.52,20.7 1.52,21.21 2.16,21.84 7.62,21.84 8.13,22.35 8.13,25.53 14.94,32.33 21.64,32.33 25.65,28.32 25.65,27.05 27.6,25.11 29.93,25.11
  vias: v1(2.16,6.07) v1(2.92,6.07) v1(24.64,15.24) v1(24.64,14.73)
VBUS_OUT_PORT_1: length 16.6
  TOP w0.254: v1(47.62,30.33) 47.49,30.46 U7.9
  TOP w0.508: R29.2 v1(47.62,30.33)
  BOTTOM w0.762: v1(47.62,30.33) C35.1 48.59,29.62 48.84,29.36 48.84,26.72 50.47,25.1 50.47,24.1 50.5,24.08 50.5,22.96 50.55,22.91 50.55,21.61 50.47,21.53 50.47,18.9 50.55,18.82 FB2.2 50.5,17.93
VBUS_OUT_PORT_2: length 18.1
  TOP w0.254: U7.8 46.99,30.73 46.58,30.33 v1(46.35,30.33)
  TOP w0.508: R30.2 v1(46.35,30.33)
  BOTTOM w0.762: FB3.2 56.21,29.64 54.48,31.37 46.91,31.37 46.35,30.81 v1(46.35,30.33) C36.1
VBUS_OUT_PORT_3: length 19.9
  BOTTOM w0.762: C40.1 43.31,21.73 43.31,24.87 44.73,26.29 44.73,29.69 43.18,31.24 38.23,31.24 37.42,30.44 FB4.2
VBUS_OUT_PORT_4: length 20.4
  BOTTOM w0.508: R32.2 23.79,27.05 23.53,26.8 22.99,26.8
  BOTTOM w0.762: FB5.2 15.21,29.64 16.88,31.32 21.26,31.32 22.63,29.95 22.63,27.15 22.99,26.8 21.34,25.15 21.34,21.46 22.35,20.45
VBUS_P1_FB: length 2
  BOTTOM w0.889: 53.4,13.78 J2.1 54.42,12.76
VBUS_P2_FB: length 2
  BOTTOM w0.889: 60.4,25.74 J3.1 61.42,26.76
VBUS_P3_FB: length 2
  BOTTOM w0.889: 39.2,26.76 J4.1 38.18,25.74
VBUS_P4_FB: length 2
  BOTTOM w0.889: 15.95,25.74 J5.1 16.97,26.76
VBUS_PUP_FB:
  vias: v1(7.17,5.18) v1(7.67,5.3)
2546_EN_PORT3: length 2.1
  TOP w0.109: R36.2 48.76,24.36 48.92,24.36 49.15,24.13 v1(49.15,23.62)
  BOTTOM w0.109: v1(49.15,23.62) 48.48,23.62 U12.5
2546_EN_PORT4: length 1.8
  BOTTOM w0.109: U13.5 26.51,23.61 26.9,24 27.29,24 R35.2
AUTO_EN: length 3.3
  TOP w0.109: v1(41.65,8.26) 41.38,8.53 40.59,8.53 U2.45
  BOTTOM w0.109: R11.1 40.75,8.15 40.86,8.26 v1(41.65,8.26)
BOARD_1P1V: length 24.2
  TOP w0.254: v1(39.75,15.88) 40.23,16.35 40.23,16.77 U2.21 ; U2.31 35.76,14.05 v1(35.76,14.17) ; U2.51 43.17,7.37 43.35,7.37 v1(43.45,7.26) ; U2.8 v1(44.47,15.28) ; U2.5 v1(45.54,14.2) ; v1(45.37,9.24) 45.34,9.27 45.34,9.5 U2.57 ; v1(37.95,14.3) 37.67,14.3 U2.28 ; U2.13 v1(42.67,17.07)
  BOTTOM w0.508: C14.1 35.89,14.17 v1(35.76,14.17) ; C10.1 42.67,16.38 v1(42.67,17.07) ; C8.1 45.94,14.59 v1(45.54,14.2) ; v1(43.45,7.26) 43.95,6.76 C12.1 ; C13.1 38.24,13.73 38.02,13.94 38.02,14.22 v1(37.95,14.3) ; C51.1 v1(11.43,18.42) ; v1(39.75,15.88) 39.31,16.31 39.31,16.81 C11.1 ; C9.1 44.7,16.12 44.47,15.88 v1(44.47,15.28) ; C7.1 v1(45.37,9.24) ; R25.1 2.27,20.57 2.78,21.08 7.75,21.08 v1(9.14,19.69)
  vias: v1(9.14,20.96) v1(9.78,20.32) v1(9.78,19.05) v1(10.41,19.69)
BOARD_3P3V: length 22.2
  TOP w0.254: v1(43.31,9.27) 42.93,8.89 42.93,8.32 U2.52 ; v1(36.5,12.85) 36.5,12.34 U2.34 ; v1(47.96,11.6) 47.55,11.6 U2.63 ; v1(41.27,17.65) 41.65,18.03 41.65,18.21 U2.16
  TOP w0.508: C18.1 35.95,6.49 v1(36.32,6.86) v1(36.96,6.22) v1(37.59,5.59) v1(38.23,4.95)
  BOTTOM w0.508: C15.1 43.31,9.65 v1(43.31,9.27) ; v1(47.96,11.6) 47.96,11.6 47.17,11.6 C17.1 ; R22.1 2.27,13.96 2.92,14.61 6.22,14.61 6.6,14.99 ; v1(41.27,17.65) 41.55,17.65 C19.1 ; U10.5 6.97,17.21 5.84,18.34 5.84,19.42 5.58,19.69 R24.1 ; v1(10.34,8.14) C46.1 ; v1(36.5,12.85) 35.79,12.85 C16.1
  vias: v1(7.24,16.51) v1(7.87,15.88) v1(7.87,14.48) v1(8.89,11.43) v1(8.89,10.16) v1(8.89,8.89) v1(9.27,9.53) v1(9.53,12.07) v1(10.16,10.16) v1(10.79,12.07) v1(36.26,2.21) v1(37.14,2.21) v1(38.01,2.21) v1(38.91,2.21)
BOARD_5V: length 21
  TOP w0.254: C53.1 23.5,25.7 23.82,25.38 23.82,25.23 23.88,25.17 v1(23.88,25.08)
  TOP w0.508: v1(45.85,25.53) 46.15,25.83 46.16,25.83 C39.1 ; R36.1 v1(48.39,25.22) ; 47.96,19.16 v1(47.29,19.18) ; v1(47.62,27.31) R29.1 R30.1
  L3_PWR w0.508: J6.1 28.27,12.6 ; J6.1 27.14,13.73 ; J6.1 26.01,12.6
  BOTTOM w0.305: v1(23.88,25.08) 23.88,24.9 24.01,24.77 U13.1 ; v1(45.85,25.53) 45.85,24.99 46.24,24.6 U12.1
  BOTTOM w0.508: R32.1 v1(24.9,27.67) ; v1(47.29,19.18) R37.1 R19.1 ; R18.1 R39.1 29.16,20.83 v1(29.69,21.36) ; C38.1 23.62,25.92 23.62,25.34 v1(23.88,25.08) ; 6.22,10.67 5.84,11.05 5.84,12.95 5.58,13.22 R21.1 ; R31.1 v1(46.47,19.16) ; R35.1 v1(29.3,24.38)
  vias: v1(6.22,8.13) v1(6.99,8.13) v1(7.75,8.13) v1(24.64,13.46) v1(25.4,12.7) v1(25.78,13.21) v1(27.94,13.97) v1(28.57,13.97) v1(28.57,13.34) v1(46.23,35.56) v1(46.86,35.56) v1(47.5,35.56) v1(48.13,35.56) v1(48.77,35.56)
DM_DN1: length 23.2
  TOP w0.112: U2.2 47.32,13.64 47.64,13.95 49.9,13.95 50.16,14.22 51.22,14.22 55.24,18.24 55.24,19.69 55.63,20.07 56.05,20.07 56.32,19.79 56.32,19.44 U3.6 56.33,19.17 56.33,18.43 U3.9 v1(56.46,17.66)
  BOTTOM w0.112: J2.2 56.92,15.59 57.54,16.21 58.13,16.21 58.31,16.38 58.31,16.76 R46.1 58.33,17.3 58.33,17.52 57.31,18.54 56.57,18.54 56.35,18.32 56.35,17.78 v1(56.46,17.66)
DM_DN2: length 25.4
  TOP w0.112: U2.10 44.46,16.51 44.83,16.88 45.56,16.88 45.67,16.99 45.9,16.99 46.02,16.88 46.34,16.88 46.46,16.99 46.66,16.99 46.78,16.88 50.02,16.88 51.12,17.98 51.12,17.98 51.58,18.44 51.58,20.1 U4.13 51.58,20.36 51.58,21.1 U4.2 v1(51.45,21.86)
  BOTTOM w0.112: J3.2 58.65,26.01 58.65,27.38 58.22,27.81 54.65,27.81 51.77,24.93 51.77,23.05 R48.1 51.61,22.29 51.61,22.05 51.45,21.88 v1(51.45,21.86)
DM_DN3: length 16.1
  TOP w0.112: v1(46.64,25.27) 46.89,25.03 46.89,24.25 47.2,23.94 47.79,23.94 48.21,23.52 48.21,22.17 47.85,21.82 47.85,20.09 47.69,19.92 43.51,19.92 43.4,19.81 41.15,19.81 40.51,19.18 40.51,18.83 40.85,18.5 U2.18
  BOTTOM w0.112: v1(46.64,25.27) 46.87,25.05 46.87,24.47 U12.2
DM_DN4: length 20.9
  TOP w0.112: U2.25 38.33,15.98 37.92,16.4 35.54,16.4 31.76,20.18 27.49,20.18 25.9,21.77 25.9,23.9 25.45,24.35 25.05,24.35 24.65,24.75 24.65,25.23 v1(24.4,25.47)
  BOTTOM w0.112: v1(24.4,25.47) 24.42,25.47 24.65,25.25 24.65,24.47 U13.2
DM_OUT3: length 23
  TOP w0.112: v1(37.2,21.86) U5.2 37.33,21.1 37.33,20.36 U5.13 37.34,20.08 37.34,19.69 37.59,19.43 38.1,19.43 39.51,20.84 42.08,20.84 43.19,21.95 45.57,21.95 46.1,21.41 46.41,21.41 46.87,20.96 46.87,20.75 v1(46.63,20.5)
  BOTTOM w0.112: v1(37.2,21.86) 37.31,21.75 37.31,21.69 37.33,21.67 37.33,21.23 37.08,20.98 36.28,20.98 35.27,21.99 35.27,23.03 35.63,23.39 36.15,23.39 36.7,23.94 J4.2 ; v1(46.63,20.5) 46.65,20.5 46.87,20.73 46.87,21.25 U12.11
DM_OUT4: length 23.1
  TOP w0.112: v1(14.97,21.86) U6.2 15.1,21.1 15.1,20.36 U6.13 15.1,20.1 15.1,19.71 15.38,19.43 17.91,19.43 20.42,21.95 23.44,21.95 23.95,21.44 24.49,21.44 24.65,21.28 24.65,20.75 v1(24.4,20.5)
  BOTTOM w0.112: U13.11 24.65,21.25 24.65,20.73 24.42,20.5 v1(24.4,20.5) ; J5.2 14.47,23.94 13.93,23.39 13.41,23.39 13.03,23.02 13.03,22 14.06,20.98 14.85,20.98 15.1,21.23 15.1,21.67 15.08,21.69 15.08,21.75 v1(14.97,21.86)
DM_UP: length 55.3
  TOP w0.112: U2.54 43.9,8.58 44.18,8.31 44.18,6.82 42.8,5.44 40.56,5.44 35.08,10.92 35.08,12.04 29.64,17.48 20.61,17.48 13.53,10.39 13.53,8.48 13.53,8.48 13.53,8.38 13.53,7.08 U1.6 13.53,6.82 13.53,6.08 U1.9 13.54,5.83 13.54,4.19 12.31,2.96 8.46,2.96 8.27,3.15 8.27,3.95 J1.2
DP_DN1: length 23.2
  TOP w0.112: U2.1 47.49,13.47 47.74,13.72 47.92,13.72 48.18,13.46 48.34,13.46 48.6,13.72 48.81,13.72 49.05,13.46 49.23,13.46 49.49,13.72 49.99,13.72 50.26,13.99 51.32,13.99 51.71,14.38 52.04,14.38 52.13,14.47 52.13,14.8 55.48,18.15 55.48,19.59 55.72,19.83 55.95,19.83 56.08,19.69 56.08,19.41 U3.7 56.09,19.17 56.09,18.43 U3.8 v1(55.96,17.67)
  BOTTOM w0.112: v1(55.96,17.67) 56.11,17.82 56.11,18.42 56.47,18.78 57.41,18.78 R45.1 58.92,16.77 J2.3
DP_DN2: length 25.4
  TOP w0.112: U2.9 44.6,16.17 44.62,16.33 44.93,16.64 50.12,16.64 51.36,17.88 51.36,17.88 51.81,18.34 51.81,20.1 U4.14 51.81,20.36 51.81,21.1 U4.1 v1(51.95,21.85)
  BOTTOM w0.112: v1(51.95,21.85) 51.95,22.09 R47.1 52,23.04 52,24.83 54.75,27.57 58.12,27.57 58.41,27.28 58.41,26.77 57.38,25.74 J3.3
DP_DN3: length 16.1
  TOP w0.112: U2.17 41.02,18.66 40.75,18.93 40.75,19.08 41.25,19.57 43.5,19.57 43.61,19.69 47.78,19.69 48.09,19.99 48.09,21.72 48.45,22.08 48.45,22.68 48.67,22.9 48.67,23.16 48.45,23.38 48.45,23.62 47.89,24.18 47.29,24.18 47.13,24.35 47.13,25.03 v1(47.37,25.27)
  BOTTOM w0.112: v1(47.37,25.27) 47.11,25.01 47.11,24.47 U12.3
DP_DN4: length 20.9
  TOP w0.112: v1(25.13,25.47) 24.88,25.23 24.88,24.85 25.15,24.59 25.55,24.59 26.14,24 26.14,23.62 26.29,23.47 26.29,23.19 26.14,23.04 26.14,22.83 26.25,22.72 26.25,22.31 26.14,22.2 26.14,21.87 27.58,20.42 31.86,20.42 35.64,16.64 38.01,16.64 38.5,16.15 U2.24
  BOTTOM w0.112: U13.3 24.88,24.47 24.88,25.23 v1(25.13,25.47)
DP_OUT3: length 23
  TOP w0.112: v1(47.35,20.5) 47.11,20.75 47.11,21.05 46.51,21.65 46.2,21.65 45.67,22.18 43.09,22.18 41.98,21.08 39.41,21.08 38,19.67 37.69,19.67 37.58,19.78 37.58,20.11 U5.14 37.56,20.36 37.56,21.1 U5.1 v1(37.7,21.85)
  BOTTOM w0.112: v1(47.35,20.5) 47.33,20.5 47.11,20.73 47.11,21.25 U12.10 ; v1(37.7,21.85) 37.57,21.72 37.57,21.13 37.18,20.74 36.18,20.74 35.03,21.89 35.03,23.25 34.7,23.58 J4.3
DP_OUT4: length 23.1
  TOP w0.112: v1(15.47,21.85) U6.1 15.34,21.1 15.34,20.36 U6.14 15.34,20.1 15.34,19.81 15.48,19.67 17.81,19.67 20.32,22.18 23.54,22.18 24.05,21.68 24.58,21.68 24.88,21.38 24.88,20.75 v1(25.13,20.5)
  BOTTOM w0.112: v1(25.13,20.5) 25.11,20.5 24.88,20.73 24.88,21.25 U13.10 ; v1(15.47,21.85) 15.34,21.72 15.34,21.13 14.95,20.74 13.96,20.74 13.82,20.88 12.79,21.91 12.79,23.26 12.47,23.58 J5.3
DP_UP: length 55.3
  TOP w0.112: J1.3 8.51,3.95 8.51,3.25 8.56,3.2 10.33,3.2 10.62,3.48 10.72,3.48 11.01,3.2 11.23,3.2 11.51,3.48 11.64,3.48 11.9,3.2 12.21,3.2 12.4,3.4 12.4,3.68 12.5,3.78 12.78,3.78 12.91,3.91 12.91,4.14 12.98,4.21 13.21,4.21 13.21,4.21 13.23,4.21 13.3,4.29 13.3,5.8 U1.8 13.29,6.08 13.29,6.82 U1.7 13.29,7.08 13.29,8.38 13.29,8.38 13.29,10.49 20.51,17.71 29.74,17.71 35.32,12.14 35.32,11.02 40.66,5.67 42.7,5.67 43.46,6.43 43.46,6.58 43.55,6.67 43.7,6.67 43.94,6.92 43.94,7.32 43.78,7.48 43.78,7.71 43.94,7.87 43.94,8.21 43.72,8.43 U2.53
EN_PORT1: length 62.4
  TOP w0.109: v1(32.32,21.37) 31.9,20.96 31.09,20.96 30.12,21.92 30.12,24.08 29.68,24.52 29.68,24.54 29.21,25.02 27.56,25.02 26.29,26.29 26.29,28.83 27.81,30.35 31.24,30.35 32.38,29.21 39.37,29.21 45.21,35.05 46.39,35.05 46.49,34.95 U7.4 ; v1(37.85,11.94) 37.57,11.67 37.27,11.67 36.9,11.3 U2.36
  BOTTOM w0.109: R15.1 36.22,4.18 36.22,4.44 36.01,4.65 36.01,5.58 35.19,6.4 35.19,7.35 35.95,8.11 35.95,10.67 37.21,11.94 v1(37.85,11.94) 38.7,11.94 38.96,12.2 39.53,12.2 39.89,12.55 39.89,13.38 37.69,15.57 37.69,15.99 v1(32.32,21.37)
EN_PORT2: length 58.8
  TOP w0.109: v1(31.57,21.36) 31.19,21.36 30.71,21.84 30.71,24.08 29.41,25.38 27.96,25.38 26.67,26.67 26.67,28.58 28.07,29.97 30.99,29.97 32.13,28.83 39.62,28.83 44.53,33.74 45.74,33.74 45.99,33.99 U7.5 ; v1(35.81,11.3) 36.07,11.3 36.42,11.66 U2.35
  BOTTOM w0.109: R14.1 35.81,4.51 35.76,4.56 35.76,5.5 34.95,6.31 34.95,7.44 35.71,8.21 35.71,10.82 35.81,10.92 v1(35.81,11.3) 36.2,11.3 37.27,12.37 38.8,12.37 38.86,12.43 39.43,12.43 39.65,12.65 39.65,13.28 v1(31.57,21.36)
FLT_PORT1#: length 36
  TOP w0.109: v1(41.64,7.62) 41.14,8.12 40.9,8.12 U2.46 ; U7.10 47.99,30.58 48.13,30.44 48.13,27.11 47.82,26.8 45.76,26.8 45.75,26.79 45.43,26.79 45.43,26.8 44.96,26.8 40.77,22.61 v1(40.77,21.59)
  BOTTOM w0.109: v1(40.77,21.59) 40.49,21.86 40.49,21.88 40.41,21.97 39.97,21.97 39.62,21.63 39.62,20.32 38.53,19.23 38.53,15.76 41.65,12.64 41.65,9.9 42.09,9.45 42.09,8.07 v1(41.64,7.62) 40.66,6.65 39.95,6.65 R12.2
FLT_PORT2#: length 33.3
  TOP w0.109: U7.6 44.93,31.22 44.58,30.86 44.58,26.93 40.13,22.49 v1(40.13,21.46) ; v1(41.15,6.1) 40.64,6.6 40.64,7.14 U2.47
  BOTTOM w0.109: v1(40.13,21.46) 40.13,20.19 38.88,18.94 38.88,15.74 41.88,12.74 41.88,10.06 42.42,9.53 42.42,7.37 v1(41.15,6.1) 40.69,6.1 R13.2
FLT_PORT3#: length 26.6
  TOP w0.109: v1(45.31,21.39) 43.51,21.39 42.44,20.32 39.75,20.32 38.48,19.05 v1(37.34,19.05) ; v1(39.79,7.12) 39.79,7.51 39.57,7.72 39.57,8.23 U2.44
  BOTTOM w0.109: U12.13 45.51,21.59 v1(45.31,21.39) ; v1(37.34,19.05) 38.23,18.16 38.23,15.73 41.41,12.54 41.41,10.11 41.4,10.1 41.4,10.06 39.6,8.26 39.6,7.69 39.79,7.51 v1(39.79,7.12) 39.67,7.24 39.29,7.24 R16.2
FLT_PORT4#: length 32.5
  TOP w0.109: U2.43 39.22,8.59 39.22,8.36 39.12,8.26 v1(39.12,7.87) ; v1(23.24,21.41) 23.24,21.03 23.27,21 23.27,20.57 23.72,20.12 25.5,20.12 v1(25.91,20.52)
  BOTTOM w0.109: v1(25.91,20.52) 26.42,20.02 29.67,20.02 31.6,21.95 32.28,21.95 37.97,16.26 37.97,15.65 41.17,12.45 41.17,10.2 39.12,8.15 v1(39.12,7.87) 38.82,7.58 R17.2 ; U13.13 23.29,21.46 v1(23.24,21.41)
GANGED: length 1.8
  TOP w0.109: v1(38.61,8.51) 38.61,8.7 U2.42
  BOTTOM w0.109: v1(38.61,8.51) 38.61,8.76 R9.1
GRST#: length 1.7
  TOP w0.254: v1(43.05,6.73) 42.87,6.91 42.87,6.94 U2.50
  BOTTOM w0.508: v1(43.05,6.73) 43.27,6.52 43.27,6.01 C6.1
HUB_SSTXM_P1: length 7.6
  TOP w0.112: C21.1 57.83,20 57.83,19.43 U3.3 57.83,19.17 57.83,18.43 U3.12 57.83,18.17 57.83,17.39 57.21,16.76 55.53,16.76 55.04,16.27 55.04,16.16 J2.8
HUB_SSTXM_P2: length 15.2
  TOP w0.112: 60.68,23.12 55.99,23.12 55.2,22.34 53.23,22.34 53.09,22.48 53.09,22.48 52.93,22.64 51.27,22.64 50.58,21.94 50.58,21.36 U4.4 50.58,21.1 50.58,20.36 U4.11 50.58,20.1 50.58,19.51 C24.1 ; 60.68,23.12 60.8,23.25 60.8,23.36 J3.8 ; 60.68,23.12 60.68,23.12
HUB_SSTXM_P3: length 7.2
  TOP w0.112: C27.1 36.33,19.51 36.33,20.1 U5.11 36.33,20.36 36.33,21.1 U5.4 36.33,21.36 36.33,22.31 36.77,22.76 38.17,22.76 38.58,23.17 38.58,23.36 J4.8
HUB_SSTXM_P4: length 7.3
  TOP w0.112: C30.1 14.1,19.49 14.1,20.07 U6.11 14.1,20.33 14.1,21.07 U6.4 14.1,21.36 14.1,22.31 14.55,22.76 15.94,22.76 16.35,23.17 16.35,23.36 J5.8
HUB_SSTXP_P1: length 7.6
  TOP w0.112: C22.1 57.59,20.02 57.59,19.42 U3.4 57.59,19.17 57.59,18.43 U3.11 57.59,18.17 57.59,17.49 57.11,17 55.43,17 54.8,16.37 54.8,16.16 J2.9
HUB_SSTXP_P2: length 15.2
  TOP w0.112: J3.9 61.04,23.36 61.04,23.15 60.92,23.03 60.92,23.03 60.78,22.89 56.09,22.89 55.3,22.1 53.13,22.1 52.99,22.24 52.99,22.24 52.83,22.4 51.37,22.4 50.81,21.84 50.81,21.36 U4.3 50.81,21.1 50.81,20.36 U4.12 50.81,20.1 50.81,19.52 C25.1
HUB_SSTXP_P3: length 7.3
  TOP w0.112: C28.1 36.57,19.52 36.57,20.1 U5.12 36.57,20.36 36.57,21.1 U5.3 36.57,21.36 36.57,22.21 36.87,22.52 38.27,22.52 38.81,23.07 38.81,23.36 J4.9
HUB_SSTXP_P4: length 7.3
  TOP w0.112: C31.1 14.34,19.49 14.34,20.07 U6.12 14.34,20.33 14.34,21.07 U6.3 14.34,21.36 14.34,22.21 14.64,22.52 16.04,22.52 16.59,23.07 16.59,23.36 J5.9
I2C_ENABLE: length 10.4
  TOP w0.109: v1(36.83,10.16) 36.95,10.04 37.79,10.04 U2.39
  BOTTOM w0.109: R5.2 38.8,4.26 38.31,4.26 37.97,4.6 37.08,4.6 36.74,4.94 36.74,5.85 35.92,6.68 35.92,7.06 36.83,7.98 v1(36.83,10.16)
I2C_SCL: length 11.9
  TOP w0.109: U2.38 37.95,10.92 v1(38.48,10.92)
  BOTTOM w0.109: v1(38.48,10.92) 36.96,10.92 36.42,10.39 36.42,8.1 36.42,7.9 35.68,7.16 35.68,6.58 36.5,5.76 36.5,4.83 37.01,4.32 37.11,4.32 37.11,4.31 37.86,4.31 R33.2
I2C_SDA: length 11.8
  TOP w0.109: v1(38.23,11.43) 37.74,11.43 U2.37
  BOTTOM w0.109: v1(38.23,11.43) 37.08,11.43 36.19,10.53 36.19,8 35.44,7.26 35.44,6.48 36.25,5.68 36.25,4.75 36.91,4.08 37.01,4.08 37.01,4.08 37.19,4.08 R1.2
JACK_INSERT:
  vias: v1(26.29,15.24) v1(26.29,14.73)
PORT3_CTL1_ILIM_SEL: length 8.8
  TOP w0.109: R42.2 45.47,27.8 v1(45.47,27.31)
  BOTTOM w0.109: U12.6 49.26,23.11 R43.1 49.08,24.34 U12.4 47.74,24.94 47.76,24.95 47.76,25.62 46.71,26.67 46.1,26.67 v1(45.47,27.31)
PORT3_CTL2_CTL3: length 3.6
  BOTTOM w0.109: U12.7 48.89,22.61 49.02,22.48 49.02,22.23 48.91,22.11 U12.8 48.47,21.31 48.97,20.8 R19.2
PORT3_STATUS#: length 1.3
  BOTTOM w0.109: U12.9 47.74,20.6 R37.2
PORT4_CTL1_ILIM_SEL: length 5.9
  TOP w0.109: v1(26.92,23.11) 26.92,23.95 v1(25.73,25.15)
  BOTTOM w0.109: U13.6 v1(26.92,23.11) 27.3,23.5 R44.2 R41.1 ; U13.4 25.52,24.94 v1(25.73,25.15)
PORT4_CTL2_CTL3: length 2.8
  BOTTOM w0.109: R18.2 27.24,21.72 26.92,22.03 26.92,22.11 ; 26.92,22.11 26.92,22.53 26.84,22.61 U13.7 ; 26.92,22.11 U13.8
PORT4_STATUS#: length 2.4
  BOTTOM w0.109: R39.2 27.12,21.39 U13.9
PWRCTL_POL: length 1.8
  TOP w0.109: v1(37.97,9.02) 38.06,9.1 38.29,9.1 U2.41
  BOTTOM w0.109: v1(37.97,9.02) 37.73,8.78 R4.2
PWRMGMT_EN#: length 2.1
  TOP w0.109: U2.40 38.12,9.65 v1(37.47,9.65)
  BOTTOM w0.109: R10.1 37.83,9.92 37.56,9.65 v1(37.47,9.65) 37.45,9.65
SSRXM_DN1: length 25.6
  TOP w0.112: U2.7 45.53,15.43 46.1,16 50.42,16 53.47,19.05 53.47,20.45 54.59,21.57 56.04,21.57 56.67,22.21 57.93,22.21 58.83,21.31 58.83,19.43 U3.1 58.83,19.17 58.83,18.43 U3.14 58.83,18.17 58.83,17.6 59.43,17 60.48,17 61.04,16.44 61.04,16.16 J2.5
SSRXM_DN2: length 18.5
  TOP w0.112: U2.15 42.67,18.31 43.14,18.78 43.68,18.78 43.79,18.67 44.51,18.67 44.73,18.9 44.98,18.9 45.21,18.67 48.68,18.67 49.08,19.06 49.08,20.09 48.95,20.22 U4.8 49.08,20.36 49.08,21.1 U4.7 49.08,21.36 49.08,22.28 50.34,23.54 53.3,23.54 53.7,23.14 54.69,23.14 54.8,23.25 54.8,23.36 J3.5
SSRXM_DN3: length 13.3
  TOP w0.112: U2.23 39.05,16.7 38.35,17.4 35.94,17.4 34.83,18.51 34.83,20.1 U5.8 34.83,20.36 34.83,21.1 U5.7 34.83,21.36 34.83,22.16 34.61,22.38 33.09,22.38 32.58,22.89 32.58,23.36 J4.5
SSRXM_DN4: length 35.1
  TOP w0.112: U2.30 36.54,14.17 36.07,14.65 34,14.65 30.4,18.24 19.76,18.24 18.53,17.01 14,17.01 12.6,18.4 12.6,20.1 U6.8 12.6,20.36 12.6,21.1 U6.7 12.6,21.36 12.6,22.16 12.39,22.38 10.86,22.38 10.35,22.89 10.35,23.36 J5.5
SSRXM_UP: length 49.5
  TOP w0.112: J1.10 16.72,4.16 16.5,4.38 16.5,4.99 16.04,5.45 16.04,5.83 U1.14 16.03,6.08 16.03,6.82 U1.1 16.03,7.08 16.03,9.87 21.99,15.84 28.48,15.84 33.53,10.8 33.53,10.4 40.07,3.85 43.32,3.85 46.41,6.93 46.41,9.68 45.7,10.39 U2.59
SSRXP_DN1: length 25.6
  TOP w0.112: U2.6 45.7,15.26 46.2,15.76 46.72,15.76 46.96,15.52 47.14,15.52 47.39,15.76 47.62,15.76 47.85,15.52 48.03,15.52 48.28,15.76 48.42,15.76 48.65,15.54 48.84,15.54 49.06,15.76 50.52,15.76 53.71,18.95 53.71,20.35 54.69,21.34 56.13,21.34 56.77,21.97 57.83,21.97 58.59,21.21 58.59,19.43 58.46,19.3 U3.2 58.59,19.17 58.59,18.43 U3.13 58.59,18.17 58.59,17.5 59.33,16.76 60.38,16.76 60.8,16.34 60.8,16.16 J2.6
SSRXP_DN2: length 18.4
  TOP w0.112: U2.14 42.85,18.16 43.24,18.54 43.58,18.54 43.69,18.43 48.78,18.43 49.31,18.96 49.31,20.1 U4.9 49.31,20.36 49.31,21.1 U4.6 49.31,21.36 49.31,22.18 50.43,23.3 53.2,23.3 53.6,22.9 54.79,22.9 55.04,23.15 55.04,23.36 J3.6
SSRXP_DN3: length 13.3
  TOP w0.112: U2.22 39.22,16.87 38.45,17.64 36.04,17.64 35.74,17.94 35.74,18.28 35.6,18.43 35.25,18.43 35.07,18.61 35.07,20.1 U5.9 35.07,20.36 35.07,21.1 U5.6 35.07,21.36 35.07,22.26 34.71,22.62 33.19,22.62 32.81,22.99 32.81,23.36 J4.6
SSRXP_DN4: length 35.1
  TOP w0.112: U2.29 36.7,14.35 36.16,14.88 34.09,14.88 33.9,15.08 33.9,15.4 33.74,15.56 33.42,15.56 30.5,18.48 19.66,18.48 18.43,17.25 14.1,17.25 12.84,18.5 12.84,20.1 U6.9 12.84,20.36 12.84,21.1 U6.6 12.84,21.36 12.84,22.26 12.49,22.62 10.96,22.62 10.59,22.99 10.59,23.36 J5.6
SSRXP_UP: length 49.5
  TOP w0.112: U2.58 45.53,10.22 46.17,9.58 46.17,9.28 46.05,9.16 46.05,8.83 46.17,8.72 46.17,8.39 46.05,8.27 46.05,7.94 46.17,7.82 46.17,7.03 43.22,4.09 40.17,4.09 33.77,10.5 33.77,10.89 28.58,16.08 21.89,16.08 15.79,9.97 ; 15.79,9.97 15.79,9.97 ; 15.79,9.97 15.79,9.97 ; 15.79,9.97 15.79,7.08 U1.2 15.79,6.82 15.79,6.08 U1.13 15.8,5.8 15.8,5.35 16.26,4.89 16.26,4.35 J1.9
SSTXM_DN1: length 15.7
  TOP w0.112: U2.4 46.57,14.35 47.07,14.86 49.15,14.86 49.4,15.11 50.8,15.11 54.36,18.67 54.36,20.07 55.1,20.81 56.42,20.81 57.02,21.41 57.58,21.41 57.65,21.35 57.77,21.23 57.85,21.15 57.85,20.87 C21.2
SSTXM_DN2: length 8.1
  TOP w0.112: C24.2 50.58,18.64 50.58,18.53 49.81,17.76 47.05,17.76 46.93,17.88 46.6,17.88 46.48,17.76 46.15,17.76 46.04,17.88 45.71,17.88 45.59,17.76 44.28,17.76 43.74,17.23 U2.12
SSTXM_DN3: length 4.9
  TOP w0.112: U2.20 40.13,17.78 39.62,18.29 38.97,18.29 38.79,18.11 36.45,18.11 36.2,18.36 C27.2
SSTXM_DN4: length 26.9
  TOP w0.112: C30.2 14.12,18.59 14.12,18.06 14.44,17.74 17.83,17.74 19.45,19.37 30.87,19.37 34.73,15.51 37.36,15.51 37.61,15.25 U2.27
SSTXM_PUP: length 4.3
  TOP w0.112: C2.1 14.79,7.79 14.79,7.08 U1.4 14.79,6.82 14.79,6.08 U1.11 14.76,5.85 14.76,5.41 14.34,4.99 14.34,4.38 J1.6
SSTXM_UP: length 44
  TOP w0.112: C3.2 15.03,8.66 15.03,10.46 21.18,16.61 29.11,16.61 34.29,11.43 34.29,10.64 40.29,4.64 43.04,4.64 45.24,6.83 45.24,8.7 44.62,9.31 U2.56
SSTXP_DN1: length 15.7
  TOP w0.112: U2.3 46.77,14.22 47.17,14.62 47.29,14.62 47.46,14.45 47.73,14.45 47.9,14.62 48.18,14.62 48.35,14.45 48.63,14.45 48.8,14.62 49.19,14.62 49.2,14.61 49.24,14.61 49.5,14.87 50.9,14.87 54.59,18.57 54.59,19.97 55.2,20.57 56.52,20.57 56.59,20.65 56.95,20.65 57.02,20.73 57.02,20.85 56.95,20.93 56.95,21.01 57.11,21.17 57.48,21.17 57.61,21.06 57.61,21.05 57.61,20.93 C22.2
SSTXP_DN2: length 8.1
  TOP w0.112: U2.11 43.9,17.05 44.38,17.53 49.91,17.53 50.82,18.43 50.82,18.64 C25.2
SSTXP_DN3: length 4.9
  TOP w0.112: U2.19 40.3,17.95 39.72,18.53 38.87,18.53 38.69,18.35 36.55,18.35 36.43,18.46 36.43,18.61 36.48,18.65 36.48,18.67 36.58,18.77 C28.2
SSTXP_DN4: length 26.9
  TOP w0.112: U2.26 37.77,15.43 37.46,15.75 34.83,15.75 34.24,16.34 34.24,16.69 34.09,16.83 33.75,16.83 30.97,19.61 19.35,19.61 17.73,17.98 14.54,17.98 14.36,18.16 14.36,18.63 C31.2
SSTXP_PUP: length 4.3
  TOP w0.112: J1.7 14.58,4.34 14.58,4.89 15,5.31 15,5.79 U1.12 15.03,6.08 15.03,6.82 U1.3 15.03,7.08 15.03,7.78 C3.1
SSTXP_UP: length 44
  TOP w0.112: U2.55 44.45,9.15 45,8.6 45,8.36 44.76,8.12 44.76,7.89 45,7.65 45,6.93 42.94,4.88 40.39,4.88 34.53,10.73 34.53,11.53 29.21,16.85 21.08,16.85 14.79,10.56 14.79,8.66 C2.2
USB_R1: length 1.6
  TOP w0.109: U2.64 47.04,12.83 v1(46.86,12.83)
  BOTTOM w0.109: v1(46.86,12.83) 46.48,12.83 R7.1
USB_VBUS_UP: length 3.5
  TOP w0.254: U2.48 41.7,6.5 41.89,6.5 v1(42.16,6.22)
  BOTTOM w0.109: R6.2 42.05,4.69
  BOTTOM w0.254: 42.05,4.69 R8.1 42.68,6.09 42.55,6.22 v1(42.16,6.22)
XI: length 9.8
  TOP w0.109: v1(48.51,10.29) 48.33,10.47 48.3,10.47 R3.2 47.52,11.25 47.18,11.25 U2.62
  BOTTOM w0.109: Y1.2 53.5,7.67 53.39,7.67 C5.1 52.51,8.55 50.25,8.55 v1(48.51,10.29)
XO: length 9.7
  TOP w0.109: v1(47.75,9.53) 47.56,9.71 47.56,9.74 R3.1 46.82,10.48 46.82,10.89 U2.61
  BOTTOM w0.109: v1(47.75,9.53) 49.73,7.54 49.73,5.79 C4.1 50.62,4.9 50.62,4.8 Y1.1
N15283: length 1.5
  BOTTOM w0.109: U9.4 7.28,13.18 R21.2
N15348:
  vias: v1(3.3,10.92) v1(3.3,10.16) v1(3.68,10.54)
N15491: length 2.3
  BOTTOM w0.109: R22.2 R23.1 3.81,12.57 3.87,12.63 U9.3
N16295: length 1.5
  BOTTOM w0.109: R24.2 7.28,19.66 U10.4
N16337:
  vias: v1(3.17,17.4) v1(3.17,16.64) v1(3.56,17.02)
N16409: length 2.3
  BOTTOM w0.109: R25.2 R26.1 3.75,19.05 3.81,19.11 U10.3
N16775579: length 8.5
  TOP w0.508: R27.2 21.56,13.94 17.78,10.16 D4.2
N16809594: length 1.3
  TOP w0.508: v1(44.72,23.86) 44.78,23.93 R34.1
  BOTTOM w0.305: U12.16 44.95,23.61 44.72,23.85 v1(44.72,23.86)
N16810447: length 1.8
  TOP w0.508: R20.1 v1(22.25,24.05)
  BOTTOM w0.305: U13.16 22.85,24.05 v1(22.25,24.05)
N16811536: length 1.3
  TOP w0.508: R38.1 v1(44.72,22.87)
  BOTTOM w0.305: v1(44.72,22.87) 44.95,23.11 U12.15
N16811977: length 1.7
  TOP w0.508: R40.1 v1(22.25,22.89)
  BOTTOM w0.305: v1(22.25,22.89) 22.5,22.89 22.73,23.11 U13.15

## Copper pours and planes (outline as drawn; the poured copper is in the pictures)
GND on TOP: 31.5,25.27 33.02,25.27 33.66,25.91 33.66,26.04 34.29,26.67 39.37,26.67 40.64,25.4 41.91,25.4 43.81,27.31 43.81,30.48 45.34,32 45.34,33.15 44.58,33.15 40.01,28.58 31.75,28.58 31.11,29.21 30.89,29.21 30.89,25.88
GND on TOP: outline of 149 points within 0.51,0.51 66.8,38.86
GND on BOTTOM: 8.71,6.2 8.71,5.13 8.89,4.95 14.22,4.95 16.38,7.11 16.38,12.98 21.06,17.65 30.61,17.65 34.87,13.39 34.98,13.39 35.31,13.72 35.31,14.35 35.56,14.61 36.58,14.61 37.06,14.12 37.13,14.12 37.62,14.61 37.62,14.96 31.62,20.96 31.11,20.96 29.84,19.69 24.03,19.69 23.75,19.41 22.12,19.41 20.57,20.96 20.57,30.23 20.32,30.48 17.02,30.48 16.13,29.59 16.13,29.13 17.37,29.13 17.91,28.6 17.91,25.27 18.54,24.64 18.54,23.5 15.37,20.32 13.72,20.32 12.32,21.72 12.32,22.99 12.06,23.24 8.99,23.24 8.76,23.01 8.76,22.1 10.54,20.32 11.68,20.32 11.94,20.07 11.94,18.03 11.68,17.78 9.65,17.78 9.27,17.4 9.27,13.69 9.3,13.67 9.3,7.9 8.74,7.34 8.26,7.34 8.26,6.65
GND on BOTTOM: 6.1,7.77 6.1,5.21 5.84,4.95 4.19,4.95 3.56,5.59 3.56,7.9 2.67,8.79 2.67,9.14 2.79,9.27 5.21,9.27 5.46,9.02 5.46,8.03 5.71,7.77
GND on BOTTOM: outline of 157 points within 0.51,0.51 66.8,38.86
GND on L2_GND: 0.51,0.51 4.19,0.51 4.32,0.64 4.32,1.14 5.97,1.14 5.97,0.64 6.1,0.51 16.64,0.51 16.76,0.64 16.76,1.14 18.54,1.14 18.54,0.64 18.67,0.51 20.32,0.51 20.42,0.61 20.42,11.58 20.93,12.09 22.23,12.09 22.61,11.71 29.84,11.71 30.23,12.09 31.75,12.09 32.16,11.68 32.16,0.61 32.26,0.51 66.8,0.51 66.8,38.86 0.51,38.86 ; 56 cut-outs
VBUS_IN on TOP: 23.77,15.27 23.77,14.58 23.88,14.48 24.77,14.48 25.02,14.73 25.22,14.73 25.27,14.78 25.27,15.24 25.02,15.49 24,15.49
